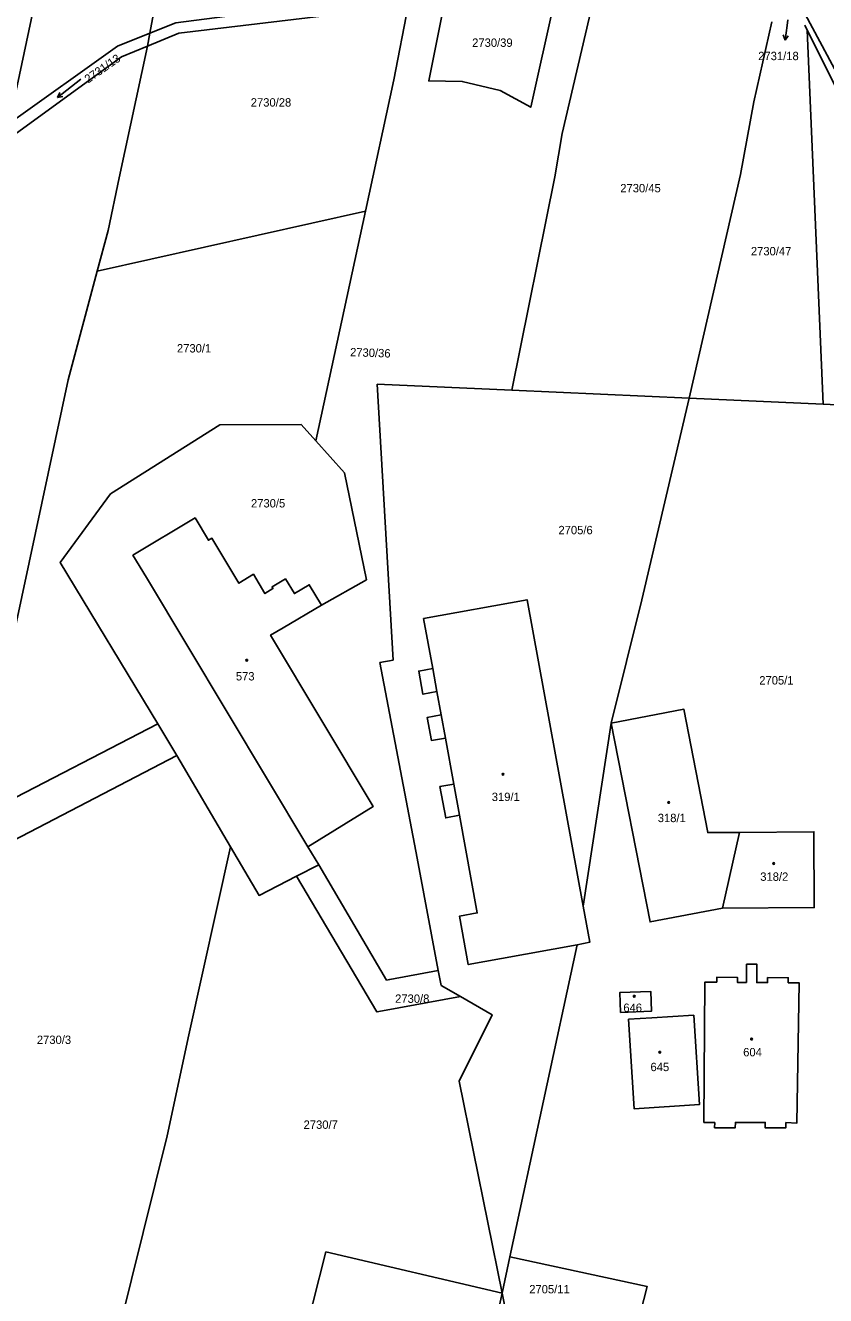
# Model space of a CAD drawing. Extents: x -755528 to -748832, y -1118122 to -1111095.
# Drawn here: x -753634.1 to -753471.7, y -1115185.5 to -1114927.7 of the extents above; entities that cross this region are included whole.
import ezdxf

# ---------------------------------------------------------------- set-up
doc = ezdxf.new("R2010")
doc.units = 0
for name, color, linetype in [('DZ_DO_ostatní', 7, 'Continuous'), ('DZ_DO_PUPFL', 7, 'Continuous'), ('DZ_NAD_ZPF', 7, 'Continuous'), ('legenda barvy', 7, 'Continuous'), ('legenda_text', 7, 'Continuous'), ('TZ_UMVŽST', 7, 'Continuous')]:
    doc.layers.add(name, color=color, linetype=linetype)

msp = doc.modelspace()

# ---------------------------------------------------------------- linework, layer by layer
at = {"layer": 'DZ_DO_ostatní'}
for p, q in [((-753550.57, -1115062.92), (-753551.42, -1115058.25)), ((-753548.85, -1115072.34), (-753549.71, -1115067.62)), ((-753545.98, -1115088.01), (-753547.14, -1115081.68))]:
    msp.add_line(p, q, dxfattribs=at)
at = {"layer": 'DZ_NAD_ZPF'}
for p, q in [((-753608.87, -1114929.33), (-753609.34, -1114931.95)), ((-753475.39, -1114928.71), (-753475.9, -1114927.69)), ((-753475.39, -1114928.71), (-753472.18, -1115004.59)), ((-753565.08, -1114965.41), (-753619.54, -1114977.59)), ((-753575.18, -1115012.02), (-753565.08, -1114965.41)), ((-753562.68, -1115000.52), (-753535.34, -1115001.75)), ((-753499.33, -1115003.37), (-753535.34, -1115001.75)), ((-753472.18, -1115004.59), (-753499.33, -1115003.37)), ((-753469.3, -1115004.72), (-753472.18, -1115004.59)), ((-753575.18, -1115012.02), (-753569.36, -1115018.51)), ((-753607.2, -1115069.43), (-753643.69, -1115088.29)), ((-753603.38, -1115075.89), (-753607.2, -1115069.43)), ((-753645.7, -1115097.86), (-753603.38, -1115075.89)), ((-753603.38, -1115075.89), (-753592.49, -1115094.39)), ((-753492.61, -1115106.84), (-753489.14, -1115091.48)), ((-753576.79, -1115094.42), (-753574.56, -1115098.09)), ((-753579.06, -1115100.39), (-753574.56, -1115098.09)), ((-753535.73, -1115177.62), (-753522.08, -1115114.32)), ((-753546.03, -1115141.95), (-753537.32, -1115185.01)), ((-753573.11, -1115176.6), (-753537.32, -1115185.01)), ((-753535.73, -1115177.62), (-753537.32, -1115185.01)), ((-753551.09, -1115247.71), (-753537.32, -1115185.01)), ((-753537.32, -1115185.01), (-753536.64, -1115188.38))]:
    msp.add_line(p, q, dxfattribs=at)
for points in [[(-753570.58, -1114761.97), (-753580.11, -1114799.28), (-753587.21, -1114828.12), (-753595.54, -1114863.4), (-753604.34, -1114904.93), (-753608.87, -1114929.33)], [(-753619.35, -1114864.71), (-753629.9, -1114912.16), (-753637.4, -1114947.63)], [(-753478.76, -1114919.85), (-753464.35, -1114946.78), (-753455.56, -1114955.73), (-753442.66, -1114964.55), (-753428.65, -1114973.62)], [(-753555.92, -1114921.01), (-753603.56, -1114927.22), (-753608.87, -1114929.33)], [(-753609.34, -1114931.95), (-753602.95, -1114929.29), (-753556.37, -1114923.73)], [(-753565.08, -1114965.41), (-753559.31, -1114938.75), (-753556.37, -1114923.73)], [(-753526.67, -1114922.71), (-753531.52, -1114944.33), (-753537.73, -1114940.93), (-753545.43, -1114939.1), (-753552.22, -1114939), (-753549.06, -1114923.44)], [(-753535.34, -1115001.75), (-753526.62, -1114958.48), (-753525.15, -1114949.67), (-753518.89, -1114923.09)], [(-753499.33, -1115003.37), (-753488.94, -1114957.99), (-753486.22, -1114943.26), (-753482.54, -1114926.98)], [(-753637.4, -1114947.63), (-753615.39, -1114931.91), (-753608.87, -1114929.33)], [(-753456.06, -1114957.63), (-753468.26, -1114942.82), (-753475.39, -1114928.71)], [(-753609.34, -1114931.95), (-753614.57, -1114934.12), (-753638.18, -1114951.25)], [(-753619.54, -1114977.59), (-753617.31, -1114969.36), (-753615.05, -1114958.63), (-753609.34, -1114931.95)], [(-753619.54, -1114977.59), (-753625.43, -1114999.63), (-753637.42, -1115055.73), (-753643.69, -1115088.29)], [(-753562.14, -1115057.04), (-753559.47, -1115056.53), (-753562.68, -1115000.52)], [(-753520.88, -1115106.45), (-753515.22, -1115069.32), (-753508.99, -1115044.31), (-753499.33, -1115003.37)], [(-753575.18, -1115012.02), (-753578.15, -1115008.7), (-753594.63, -1115008.78), (-753616.83, -1115022.81), (-753627.02, -1115036.71), (-753607.2, -1115069.43)], [(-753569.36, -1115018.51), (-753564.85, -1115040.22), (-753574.02, -1115045.36)], [(-753574.02, -1115045.36), (-753576.5, -1115041.25), (-753579.51, -1115043.02), (-753581.31, -1115040.06), (-753584.03, -1115041.64), (-753583.87, -1115042.02), (-753585.5, -1115043.02), (-753587.83, -1115039.12), (-753590.77, -1115040.92), (-753596.25, -1115031.79), (-753596.94, -1115032.21), (-753599.66, -1115027.69), (-753612.27, -1115035.24), (-753609.5, -1115039.74), (-753576.79, -1115094.42)], [(-753574.02, -1115045.36), (-753581.79, -1115049.98), (-753584.35, -1115051.46), (-753563.53, -1115086.24), (-753576.79, -1115094.42)], [(-753520.88, -1115106.45), (-753532.25, -1115044.28), (-753553.27, -1115048.1), (-753551.42, -1115058.25), (-753554.24, -1115058.77), (-753553.4, -1115063.45), (-753550.57, -1115062.92), (-753549.71, -1115067.62), (-753552.52, -1115068.16), (-753551.67, -1115072.83), (-753548.85, -1115072.34), (-753547.14, -1115081.68), (-753549.94, -1115082.2), (-753548.78, -1115088.55), (-753545.98, -1115088.01), (-753542.36, -1115107.84), (-753545.99, -1115108.51), (-753544.2, -1115118.33), (-753537.48, -1115117.11), (-753522.08, -1115114.32)], [(-753550.28, -1115119.53), (-753554.6, -1115096.75), (-753562.14, -1115057.04)], [(-753489.14, -1115091.48), (-753495.57, -1115091.53), (-753500.42, -1115066.49), (-753515.22, -1115069.32), (-753507.29, -1115109.65), (-753492.61, -1115106.84)], [(-753492.61, -1115106.84), (-753473.96, -1115106.74), (-753474.04, -1115091.36), (-753489.14, -1115091.48)], [(-753622.14, -1115213.44), (-753617.46, -1115201.86), (-753605.32, -1115153.08), (-753600.94, -1115132.59), (-753592.49, -1115094.39)], [(-753592.49, -1115094.39), (-753586.67, -1115104.28), (-753579.06, -1115100.39)], [(-753574.56, -1115098.09), (-753560.77, -1115121.46), (-753560.14, -1115121.34), (-753550.28, -1115119.53)], [(-753545.79, -1115124.8), (-753561.64, -1115127.73), (-753562.75, -1115127.93), (-753579.06, -1115100.39)], [(-753520.88, -1115106.45), (-753519.54, -1115113.77), (-753522.08, -1115114.32)], [(-753493.75, -1115121.9), (-753493.74, -1115120.9), (-753489.56, -1115120.93), (-753489.57, -1115121.93), (-753487.72, -1115121.94), (-753487.69, -1115118.24), (-753485.59, -1115118.26), (-753485.62, -1115121.96), (-753483.44, -1115121.97), (-753483.43, -1115120.97), (-753479.25, -1115121), (-753479.26, -1115122)], [(-753550.28, -1115119.53), (-753549.71, -1115122.53), (-753545.79, -1115124.8)], [(-753479.26, -1115122), (-753477.05, -1115122.02), (-753477.48, -1115150.47), (-753479.7, -1115150.39), (-753479.74, -1115151.48), (-753483.91, -1115151.48), (-753483.9, -1115150.36), (-753489.98, -1115150.36), (-753490, -1115151.44), (-753494.18, -1115151.42), (-753494.16, -1115150.39), (-753496.36, -1115150.35), (-753496.15, -1115121.88), (-753493.75, -1115121.9)], [(-753545.79, -1115124.8), (-753539.38, -1115128.51), (-753546.03, -1115141.95)], [(-753513.32, -1115128.02), (-753507.01, -1115127.78), (-753507.17, -1115123.75), (-753513.46, -1115123.99), (-753513.32, -1115128.02)], [(-753511.68, -1115129.39), (-753510.54, -1115147.58), (-753497.27, -1115146.74), (-753498.41, -1115128.6), (-753506.96, -1115129.11), (-753511.68, -1115129.39)], [(-753593.11, -1115253.06), (-753583.65, -1115218.26), (-753573.11, -1115176.6)], [(-753535.73, -1115177.62), (-753507.87, -1115183.65), (-753511.13, -1115196.3)]]:
    msp.add_lwpolyline(points, dxfattribs=at)
at = {"layer": 'legenda barvy'}
for p, q in [((-753479.33, -1114926.6), (-753479.48, -1114927.76)), ((-753479.898, -1114930.732), (-753480.254, -1114929.67)), ((-753479.48, -1114927.76), (-753479.898, -1114930.732)), ((-753479.898, -1114930.732), (-753479.262, -1114929.81))]:
    msp.add_line(p, q, dxfattribs=at)
at = {"layer": 'legenda_text'}
for centre in [(-753589.1768, -1115056.5492), (-753537.1468, -1115079.6892), (-753503.5168, -1115085.4192), (-753482.2068, -1115097.7992), (-753510.5068, -1115124.7392), (-753486.6868, -1115133.4392), (-753505.3168, -1115136.0992)]:
    msp.add_circle(centre, 0.175, dxfattribs=at)
at = {"layer": 'TZ_UMVŽST'}
for p, q in [((-753622.885, -1114938.637), (-753627.613, -1114942.331)), ((-753627.613, -1114942.331), (-753627.152, -1114941.334)), ((-753627.613, -1114942.331), (-753626.534, -1114942.124))]:
    msp.add_line(p, q, dxfattribs=at)

# ---------------------------------------------------------------- texts
at = {"layer": 'DZ_DO_PUPFL'}
for s, p in [('2730/39', (-753543.41, -1114932.08)), ('2731/18', (-753485.333, -1114934.778)), ('2730/28', (-753588.36, -1114944.2)), ('2730/45', (-753513.34, -1114961.6)), ('2730/47', (-753486.82, -1114974.39)), ('2730/1', (-753603.34, -1114994.1)), ('2730/5', (-753588.31, -1115025.55)), ('2705/6', (-753525.89, -1115030.99)), ('573', (-753591.38, -1115060.66)), ('2705/1', (-753485.12, -1115061.48)), ('319/1', (-753539.43, -1115085.13)), ('318/1', (-753505.73, -1115089.41)), ('318/2', (-753484.92, -1115101.32)), ('2730/8', (-753559.05, -1115126.08)), ('646', (-753512.715, -1115127.93)), ('2730/3', (-753631.78, -1115134.43)), ('604', (-753488.39, -1115136.94)), ('645', (-753507.205, -1115139.94)), ('2730/7', (-753577.63, -1115151.65)), ('2705/11', (-753531.82, -1115185.04))]:
    msp.add_text(s, height=1.7, dxfattribs=at).set_placement(p)
for s, rotation, p in [('2731/13', 35, (-753621.362, -1114939.526)), ('2730/36', 358, (-753568.219, -1114994.859))]:
    msp.add_text(s, height=1.7, rotation=rotation, dxfattribs=at).set_placement(p)

doc.saveas('drawing.dxf')
